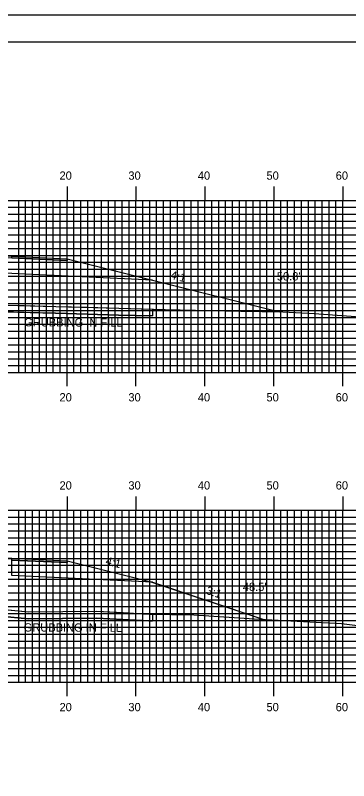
# Model space of a CAD drawing. Extents: x 1813735 to 1814078, y 442591 to 442811.
# Drawn here: x 1813913 to 1813961.3, y 442699.4 to 442810.5 of the extents above; entities that cross this region are included whole.
import ezdxf

# ---------------------------------------------------------------- set-up
doc = ezdxf.new("R2010")
doc.units = 0
for name, color, linetype in [('ANNOTATION', 7, 'Continuous'), ('BORDER', 7, 'Continuous'), ('D_Roadway_Centerline', 7, 'Continuous'), ('D_Roadway_Edge_Shoulder', 7, 'Continuous'), ('D_Roadway_SlopeLines', 7, 'Continuous'), ('D_Roadway_SubGrade', 7, 'Continuous'), ('D_Text_Standard', 7, 'Continuous'), ('GRUBBING IN FILL', 7, 'Continuous'), ('H_V ANNOTATION', 7, 'Continuous'), ('MAJOR', 7, 'Continuous'), ('MINOR', 7, 'Continuous'), ('PLOT BOUNDARY', 7, 'Continuous'), ('S_Roadway_Centerline', 7, 'Continuous')]:
    doc.layers.add(name, color=color, linetype=linetype)

msp = doc.modelspace()

# ---------------------------------------------------------------- linework, layer by layer
at = {"layer": 'BORDER'}
msp.add_lwpolyline([(1813750.88, 442596.67), (1814070.88, 442596.67), (1814070.88, 442806.67), (1813750.88, 442806.67)], close=True, dxfattribs=at)
at = {"layer": 'D_Roadway_Centerline'}
for points in [[(1813847.58, 442770.6), (1813858.58, 442773.35), (1813859.71, 442773.63), (1813870.58, 442776.35), (1813888.48, 442776.71), (1813900.48, 442776.13), (1813912.48, 442775.56), (1813920.48, 442775.17), (1813932.86, 442772.08), (1813951.3, 442767.47)], [(1813856.67, 442725.68), (1813869.5, 442729.95), (1813877.48, 442732.61), (1813880.48, 442732.67), (1813888.48, 442732.83), (1813900.48, 442732.26), (1813912.48, 442731.68), (1813920.48, 442731.3), (1813932.48, 442728.3), (1813932.86, 442728.2), (1813949.02, 442722.79)]]:
    msp.add_lwpolyline(points, dxfattribs=at)
at = {"layer": 'D_Roadway_Edge_Shoulder'}
for points in [[(1813912.48, 442775.56), (1813920.48, 442775.17), (1813920.48, 442774.92), (1813912.48, 442775.31)], [(1813912.48, 442731.68), (1813920.48, 442731.3), (1813920.48, 442731.05), (1813912.48, 442731.43)]]:
    msp.add_lwpolyline(points, close=True, dxfattribs=at)
at = {"layer": 'D_Roadway_SlopeLines'}
for points in [[(1813920.48, 442775.17), (1813932.86, 442772.08), (1813951.3, 442767.47)], [(1813920.48, 442731.3), (1813932.48, 442728.3), (1813949.02, 442722.79)]]:
    msp.add_lwpolyline(points, dxfattribs=at)
at = {"layer": 'D_Roadway_SubGrade'}
for points in [[(1813888.48, 442774.21), (1813859.71, 442773.63), (1813870.58, 442776.35), (1813870.58, 442776.1), (1813888.48, 442776.46), (1813900.48, 442775.88), (1813912.48, 442775.31), (1813920.48, 442774.92), (1813920.48, 442775.17), (1813932.86, 442772.08), (1813912.48, 442773.06), (1813900.48, 442773.63)], [(1813912.48, 442731.02), (1813912.48, 442731.43), (1813920.48, 442731.05), (1813920.48, 442731.3), (1813932.86, 442728.2), (1813912.48, 442729.18)]]:
    msp.add_lwpolyline(points, close=True, dxfattribs=at)
at = {"layer": 'GRUBBING IN FILL'}
for p, q in [((1813932.86, 442767.88), (1813932.86, 442766.88)), ((1813932.86, 442767.88), (1813932.86, 442766.88)), ((1813932.86, 442723.58), (1813932.86, 442722.58)), ((1813932.86, 442723.58), (1813932.86, 442722.58))]:
    msp.add_line(p, q, dxfattribs=at)
for points in [[(1813859.71, 442768.99), (1813865.57, 442768.74), (1813886.63, 442768.16), (1813894.34, 442768.16), (1813901.55, 442767.95), (1813909.6, 442767.51), (1813918.82, 442767.27), (1813927.96, 442767.02), (1813932.86, 442766.88)], [(1813859.71, 442768.99), (1813865.57, 442768.74), (1813886.63, 442768.16), (1813894.34, 442768.16), (1813901.55, 442767.95), (1813909.6, 442767.51), (1813918.82, 442767.27), (1813927.96, 442767.02), (1813932.86, 442766.88)], [(1813869.5, 442724.56), (1813871.07, 442724.54), (1813882.58, 442724.31), (1813888.12, 442724.25), (1813898.38, 442723.87), (1813907.78, 442723.57), (1813914.86, 442722.91), (1813924.78, 442722.99), (1813932.35, 442722.59), (1813932.86, 442722.58)], [(1813869.5, 442724.56), (1813871.07, 442724.54), (1813882.58, 442724.31), (1813888.12, 442724.25), (1813898.38, 442723.87), (1813907.78, 442723.57), (1813914.86, 442722.91), (1813924.78, 442722.99), (1813932.35, 442722.59), (1813932.86, 442722.58)]]:
    msp.add_lwpolyline(points, dxfattribs=at)
for points in [[(1813900.48, 442768.99), (1813901.59, 442768.95), (1813909.64, 442768.51), (1813914.25, 442768.39), (1813918.85, 442768.27), (1813923.42, 442768.15), (1813927.99, 442768.02), (1813932.86, 442767.88), (1813932.86, 442766.88), (1813927.96, 442767.02), (1813923.39, 442767.15), (1813918.82, 442767.27), (1813914.21, 442767.39), (1813909.6, 442767.51), (1813901.55, 442767.95), (1813900.48, 442767.99)], [(1813900.48, 442768.99), (1813901.59, 442768.95), (1813909.64, 442768.51), (1813914.25, 442768.39), (1813918.85, 442768.27), (1813923.42, 442768.15), (1813927.99, 442768.02), (1813932.86, 442767.88), (1813932.86, 442766.88), (1813927.96, 442767.02), (1813923.39, 442767.15), (1813918.82, 442767.27), (1813914.21, 442767.39), (1813909.6, 442767.51), (1813901.55, 442767.95), (1813900.48, 442767.99)], [(1813900.48, 442724.8), (1813903.12, 442724.72), (1813907.84, 442724.57), (1813911.48, 442724.23), (1813914.9, 442723.91), (1813919.85, 442723.95), (1813924.8, 442723.99), (1813928.6, 442723.79), (1813932.39, 442723.59), (1813932.86, 442723.58), (1813932.86, 442722.58), (1813932.35, 442722.59), (1813928.57, 442722.79), (1813924.78, 442722.99), (1813919.82, 442722.95), (1813914.86, 442722.91), (1813911.32, 442723.24), (1813907.78, 442723.57), (1813903.08, 442723.72), (1813900.48, 442723.8)], [(1813900.48, 442724.8), (1813903.12, 442724.72), (1813907.84, 442724.57), (1813911.48, 442724.23), (1813914.9, 442723.91), (1813919.85, 442723.95), (1813924.8, 442723.99), (1813928.6, 442723.79), (1813932.39, 442723.59), (1813932.86, 442723.58), (1813932.86, 442722.58), (1813932.35, 442722.59), (1813928.57, 442722.79), (1813924.78, 442722.99), (1813919.82, 442722.95), (1813914.86, 442722.91), (1813911.32, 442723.24), (1813907.78, 442723.57), (1813903.08, 442723.72), (1813900.48, 442723.8)]]:
    msp.add_lwpolyline(points, close=True, dxfattribs=at)
at = {"layer": 'MAJOR'}
for p, q in [((1813920.48, 442785.67), (1813920.48, 442783.67)), ((1813930.48, 442785.67), (1813930.48, 442783.67)), ((1813940.48, 442785.67), (1813940.48, 442783.67)), ((1813950.48, 442785.67), (1813950.48, 442783.67)), ((1813960.48, 442785.67), (1813960.48, 442783.67)), ((1813760.48, 442783.67), (1814040.48, 442783.67)), ((1813760.48, 442783.67), (1814040.48, 442783.67)), ((1813920.48, 442758.67), (1813920.48, 442783.67)), ((1813930.48, 442758.67), (1813930.48, 442783.67)), ((1813940.48, 442758.67), (1813940.48, 442783.67)), ((1813950.48, 442758.67), (1813950.48, 442783.67)), ((1813960.48, 442758.67), (1813960.48, 442783.67)), ((1813760.48, 442778.67), (1814040.48, 442778.67)), ((1813760.48, 442773.67), (1814040.48, 442773.67)), ((1813760.48, 442768.67), (1814040.48, 442768.67)), ((1813760.48, 442763.67), (1814040.48, 442763.67)), ((1813760.48, 442758.67), (1814040.48, 442758.67)), ((1813760.48, 442758.67), (1814040.48, 442758.67)), ((1813920.48, 442756.66), (1813920.48, 442758.67)), ((1813930.48, 442756.66), (1813930.48, 442758.67)), ((1813940.48, 442756.66), (1813940.48, 442758.67)), ((1813950.48, 442756.66), (1813950.48, 442758.67)), ((1813960.48, 442756.66), (1813960.48, 442758.67)), ((1813920.48, 442740.67), (1813920.48, 442738.67)), ((1813930.48, 442740.67), (1813930.48, 442738.67)), ((1813940.48, 442740.67), (1813940.48, 442738.67)), ((1813950.48, 442740.67), (1813950.48, 442738.67)), ((1813960.48, 442740.67), (1813960.48, 442738.67)), ((1813760.48, 442738.67), (1814040.48, 442738.67)), ((1813760.48, 442738.67), (1814040.48, 442738.67)), ((1813920.48, 442713.67), (1813920.48, 442738.67)), ((1813930.48, 442713.67), (1813930.48, 442738.67)), ((1813940.48, 442713.67), (1813940.48, 442738.67)), ((1813950.48, 442713.67), (1813950.48, 442738.67)), ((1813960.48, 442713.67), (1813960.48, 442738.67)), ((1813760.48, 442733.67), (1814040.48, 442733.67)), ((1813760.48, 442728.67), (1814040.48, 442728.67)), ((1813760.48, 442723.67), (1814040.48, 442723.67)), ((1813760.48, 442718.67), (1814040.48, 442718.67)), ((1813760.48, 442713.67), (1814040.48, 442713.67)), ((1813760.48, 442713.67), (1814040.48, 442713.67)), ((1813920.48, 442711.66), (1813920.48, 442713.67)), ((1813930.48, 442711.66), (1813930.48, 442713.67)), ((1813940.48, 442711.66), (1813940.48, 442713.67)), ((1813950.48, 442711.66), (1813950.48, 442713.67)), ((1813960.48, 442711.66), (1813960.48, 442713.67))]:
    msp.add_line(p, q, dxfattribs=at)
at = {"layer": 'MINOR'}
for p, q in [((1813913.48, 442758.67), (1813913.48, 442783.67)), ((1813914.48, 442758.67), (1813914.48, 442783.67)), ((1813915.48, 442758.67), (1813915.48, 442783.67)), ((1813916.48, 442758.67), (1813916.48, 442783.67)), ((1813917.48, 442758.67), (1813917.48, 442783.67)), ((1813918.48, 442758.67), (1813918.48, 442783.67)), ((1813919.48, 442758.67), (1813919.48, 442783.67)), ((1813921.48, 442758.67), (1813921.48, 442783.67)), ((1813922.48, 442758.67), (1813922.48, 442783.67)), ((1813923.48, 442758.67), (1813923.48, 442783.67)), ((1813924.48, 442758.67), (1813924.48, 442783.67)), ((1813925.48, 442758.67), (1813925.48, 442783.67)), ((1813926.48, 442758.67), (1813926.48, 442783.67)), ((1813927.48, 442758.67), (1813927.48, 442783.67)), ((1813928.48, 442758.67), (1813928.48, 442783.67)), ((1813929.48, 442758.67), (1813929.48, 442783.67)), ((1813931.48, 442758.67), (1813931.48, 442783.67)), ((1813932.48, 442758.67), (1813932.48, 442783.67)), ((1813933.48, 442758.67), (1813933.48, 442783.67)), ((1813934.48, 442758.67), (1813934.48, 442783.67)), ((1813935.48, 442758.67), (1813935.48, 442783.67)), ((1813936.48, 442758.67), (1813936.48, 442783.67)), ((1813937.48, 442758.67), (1813937.48, 442783.67)), ((1813938.48, 442758.67), (1813938.48, 442783.67)), ((1813939.48, 442758.67), (1813939.48, 442783.67)), ((1813941.48, 442758.67), (1813941.48, 442783.67)), ((1813942.48, 442758.67), (1813942.48, 442783.67)), ((1813943.48, 442758.67), (1813943.48, 442783.67)), ((1813944.48, 442758.67), (1813944.48, 442783.67)), ((1813945.48, 442758.67), (1813945.48, 442783.67)), ((1813946.48, 442758.67), (1813946.48, 442783.67)), ((1813947.48, 442758.67), (1813947.48, 442783.67)), ((1813948.48, 442758.67), (1813948.48, 442783.67)), ((1813949.48, 442758.67), (1813949.48, 442783.67)), ((1813951.48, 442758.67), (1813951.48, 442783.67)), ((1813952.48, 442758.67), (1813952.48, 442783.67)), ((1813953.48, 442758.67), (1813953.48, 442783.67)), ((1813954.48, 442758.67), (1813954.48, 442783.67)), ((1813955.48, 442758.67), (1813955.48, 442783.67)), ((1813956.48, 442758.67), (1813956.48, 442783.67)), ((1813957.48, 442758.67), (1813957.48, 442783.67)), ((1813958.48, 442758.67), (1813958.48, 442783.67)), ((1813959.48, 442758.67), (1813959.48, 442783.67)), ((1813760.48, 442782.67), (1814040.48, 442782.67)), ((1813760.48, 442781.67), (1814040.48, 442781.67)), ((1813760.48, 442780.67), (1814040.48, 442780.67)), ((1813760.48, 442779.67), (1814040.48, 442779.67)), ((1813760.48, 442777.67), (1814040.48, 442777.67)), ((1813760.48, 442776.67), (1814040.48, 442776.67)), ((1813760.48, 442775.67), (1814040.48, 442775.67)), ((1813760.48, 442774.67), (1814040.48, 442774.67)), ((1813760.48, 442772.67), (1814040.48, 442772.67)), ((1813760.48, 442771.67), (1814040.48, 442771.67)), ((1813760.48, 442770.67), (1814040.48, 442770.67)), ((1813760.48, 442769.67), (1814040.48, 442769.67)), ((1813760.48, 442767.67), (1814040.48, 442767.67)), ((1813760.48, 442766.67), (1814040.48, 442766.67)), ((1813760.48, 442765.67), (1814040.48, 442765.67)), ((1813760.48, 442764.67), (1814040.48, 442764.67)), ((1813760.48, 442762.67), (1814040.48, 442762.67)), ((1813760.48, 442761.67), (1814040.48, 442761.67)), ((1813760.48, 442760.67), (1814040.48, 442760.67)), ((1813760.48, 442759.67), (1814040.48, 442759.67)), ((1813913.48, 442713.67), (1813913.48, 442738.67)), ((1813914.48, 442713.67), (1813914.48, 442738.67)), ((1813915.48, 442713.67), (1813915.48, 442738.67)), ((1813916.48, 442713.67), (1813916.48, 442738.67)), ((1813917.48, 442713.67), (1813917.48, 442738.67)), ((1813918.48, 442713.67), (1813918.48, 442738.67)), ((1813919.48, 442713.67), (1813919.48, 442738.67)), ((1813921.48, 442713.67), (1813921.48, 442738.67)), ((1813922.48, 442713.67), (1813922.48, 442738.67)), ((1813923.48, 442713.67), (1813923.48, 442738.67)), ((1813924.48, 442713.67), (1813924.48, 442738.67)), ((1813925.48, 442713.67), (1813925.48, 442738.67)), ((1813926.48, 442713.67), (1813926.48, 442738.67)), ((1813927.48, 442713.67), (1813927.48, 442738.67)), ((1813928.48, 442713.67), (1813928.48, 442738.67)), ((1813929.48, 442713.67), (1813929.48, 442738.67)), ((1813931.48, 442713.67), (1813931.48, 442738.67)), ((1813932.48, 442713.67), (1813932.48, 442738.67)), ((1813933.48, 442713.67), (1813933.48, 442738.67)), ((1813934.48, 442713.67), (1813934.48, 442738.67)), ((1813935.48, 442713.67), (1813935.48, 442738.67)), ((1813936.48, 442713.67), (1813936.48, 442738.67)), ((1813937.48, 442713.67), (1813937.48, 442738.67)), ((1813938.48, 442713.67), (1813938.48, 442738.67)), ((1813939.48, 442713.67), (1813939.48, 442738.67)), ((1813941.48, 442713.67), (1813941.48, 442738.67)), ((1813942.48, 442713.67), (1813942.48, 442738.67)), ((1813943.48, 442713.67), (1813943.48, 442738.67)), ((1813944.48, 442713.67), (1813944.48, 442738.67)), ((1813945.48, 442713.67), (1813945.48, 442738.67)), ((1813946.48, 442713.67), (1813946.48, 442738.67)), ((1813947.48, 442713.67), (1813947.48, 442738.67)), ((1813948.48, 442713.67), (1813948.48, 442738.67)), ((1813949.48, 442713.67), (1813949.48, 442738.67)), ((1813951.48, 442713.67), (1813951.48, 442738.67)), ((1813952.48, 442713.67), (1813952.48, 442738.67)), ((1813953.48, 442713.67), (1813953.48, 442738.67)), ((1813954.48, 442713.67), (1813954.48, 442738.67)), ((1813955.48, 442713.67), (1813955.48, 442738.67)), ((1813956.48, 442713.67), (1813956.48, 442738.67)), ((1813957.48, 442713.67), (1813957.48, 442738.67)), ((1813958.48, 442713.67), (1813958.48, 442738.67)), ((1813959.48, 442713.67), (1813959.48, 442738.67)), ((1813760.48, 442737.67), (1814040.48, 442737.67)), ((1813760.48, 442736.67), (1814040.48, 442736.67)), ((1813760.48, 442735.67), (1814040.48, 442735.67)), ((1813760.48, 442734.67), (1814040.48, 442734.67)), ((1813760.48, 442732.67), (1814040.48, 442732.67)), ((1813760.48, 442731.67), (1814040.48, 442731.67)), ((1813760.48, 442730.67), (1814040.48, 442730.67)), ((1813760.48, 442729.67), (1814040.48, 442729.67)), ((1813760.48, 442727.67), (1814040.48, 442727.67)), ((1813760.48, 442726.67), (1814040.48, 442726.67)), ((1813760.48, 442725.67), (1814040.48, 442725.67)), ((1813760.48, 442724.67), (1814040.48, 442724.67)), ((1813760.48, 442722.67), (1814040.48, 442722.67)), ((1813760.48, 442721.67), (1814040.48, 442721.67)), ((1813760.48, 442720.67), (1814040.48, 442720.67)), ((1813760.48, 442719.67), (1814040.48, 442719.67)), ((1813760.48, 442717.67), (1814040.48, 442717.67)), ((1813760.48, 442716.67), (1814040.48, 442716.67)), ((1813760.48, 442715.67), (1814040.48, 442715.67)), ((1813760.48, 442714.67), (1814040.48, 442714.67))]:
    msp.add_line(p, q, dxfattribs=at)
at = {"layer": 'PLOT BOUNDARY'}
msp.add_lwpolyline([(1813734.69, 442590.55), (1814074.69, 442590.55), (1814074.69, 442810.55), (1813734.69, 442810.55)], close=True, dxfattribs=at)
at = {"layer": 'S_Roadway_Centerline'}
for points in [[(1813760.48, 442772.66), (1813778.12, 442772.11), (1813786.67, 442771.82), (1813787.25, 442771.82), (1813803.28, 442771.39), (1813803.78, 442771.39), (1813818.39, 442771.2), (1813820.44, 442771.08), (1813833.26, 442771.04), (1813836.69, 442770.97), (1813841.59, 442770.94), (1813854.06, 442770.23), (1813865.61, 442769.74), (1813886.64, 442769.16), (1813894.36, 442769.16), (1813901.59, 442768.95), (1813909.64, 442768.51), (1813918.85, 442768.27), (1813927.99, 442768.02), (1813934.7, 442767.83), (1813945.69, 442767.6), (1813951.79, 442767.46), (1813956.33, 442767.23), (1813968.35, 442766.36)], [(1813831.93, 442726.82), (1813846.29, 442725.84), (1813848.21, 442725.81), (1813850.94, 442725.72), (1813866.26, 442725.61), (1813871.09, 442725.54), (1813882.6, 442725.31), (1813888.14, 442725.25), (1813898.41, 442724.87), (1813907.84, 442724.57), (1813914.9, 442723.91), (1813924.8, 442723.99), (1813932.39, 442723.59), (1813938.88, 442723.46), (1813948.37, 442722.82), (1813960.29, 442722.2), (1813964.48, 442721.67)]]:
    msp.add_lwpolyline(points, dxfattribs=at)

# ---------------------------------------------------------------- texts
at = {"layer": 'ANNOTATION'}
for s, rotation, p in [('4:1', 345.9638, (1813935.4, 442772.31)), ('4:1', 345.9638, (1813925.99, 442730.78)), ('3:1', 341.4652, (1813940.55, 442726.54))]:
    msp.add_text(s, height=1.2, rotation=rotation, dxfattribs=at).set_placement(p)
at = {"layer": 'D_Text_Standard'}
for s, p in [("50.8'", (1813950.91, 442772.04)), ("48.5'", (1813945.98, 442726.94))]:
    msp.add_text(s, height=1.2, dxfattribs=at).set_placement(p)
at = {"layer": 'GRUBBING IN FILL'}
for p in [(1813914.27, 442765.37), (1813914.19, 442721.05)]:
    msp.add_text('GRUBBING IN FILL', height=1.2, rotation=359.8053, dxfattribs=at).set_placement(p)
at = {"layer": 'H_V ANNOTATION'}
for s, p in [('20', (1813919.39, 442786.67)), ('30', (1813929.38, 442786.67)), ('40', (1813939.45, 442786.67)), ('50', (1813949.41, 442786.67)), ('60', (1813959.45, 442786.67)), ('20', (1813919.39, 442754.47)), ('30', (1813929.38, 442754.47)), ('40', (1813939.45, 442754.47)), ('50', (1813949.41, 442754.47)), ('60', (1813959.45, 442754.47)), ('20', (1813919.39, 442741.67)), ('30', (1813929.38, 442741.67)), ('40', (1813939.45, 442741.67)), ('50', (1813949.41, 442741.67)), ('60', (1813959.45, 442741.67)), ('20', (1813919.39, 442709.47)), ('30', (1813929.38, 442709.47)), ('40', (1813939.45, 442709.47)), ('50', (1813949.41, 442709.47)), ('60', (1813959.45, 442709.47))]:
    msp.add_text(s, height=1.2, dxfattribs=at).set_placement(p)

doc.saveas('drawing.dxf')
